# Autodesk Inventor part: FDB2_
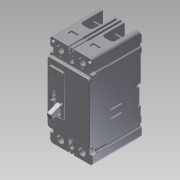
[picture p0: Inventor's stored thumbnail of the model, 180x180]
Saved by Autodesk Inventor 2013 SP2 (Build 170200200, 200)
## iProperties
Created: 2014-08
Part Number: FDB2_
Material: Generic
Document SubType Name: Modeling
Designer: DM/JS
Density: 1 g/cm^3
Description: TYPE FDB THERMAL MAGNETIC CIRCUIT BREAKERS TWO POLE, SERIES C
Translation Standard: STEP AP214IS
FileName: Y:\ECO-062745\WIP\New\FD2_.stp
PreProcessor: Autodesk Inventor 2012
PostProcessor: Build: 219, Release: 2012 SP2 - Date: Fri 04/27/2012
Sent Units: inch
Uncertainty: 0.00039370078740199997
MXEDIT: false
MXINVTNRV: INV Versioned Component|FDB2_|002.0
Author: DM/JS
Revision Number: 003
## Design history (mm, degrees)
node "FDB2_"
node "L1"
node "L2"
node "T1"
node "T2"
body "Solid1"
node "Base1"
